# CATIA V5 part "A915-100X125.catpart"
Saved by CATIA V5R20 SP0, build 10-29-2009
Part number: A915-100X125
Source: Unknown
Property "A": "0.000"
Property "ARTICLENO": "A915-100X125"
Property "BOMINFO": "A915-100X125"
Property "CODE": "A915-100X125"
Property "CREATOR": "CADENAS GmbH"
Property "D": "13.500"
Property "D1": "20.000"
Property "FORM": "B"
Property "L": "125.000"
Property "L1": "25.000"
Property "L2": "75.000"
Property "LINA": "A915-100X125"
Property "NB": "A915-100X125"
Property "NBSYN": "$CODE."
Property "NN": "A915"
Property "NT": "VDI 3357 Wear Plates, steel"
Property "SCREW": "M12x25"
Property "SUPPLIER": "CF"
Property "T": "13.000"
Property "W": "100.000"
Bounding box of the stored display mesh (mm): x 0 to 20, y 0 to 125, z -50 to 50
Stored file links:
  C:\Users\borellobunino\Desktop\3D X SITO CF\A915\GSB_OILLESS_G22501100125\CATIAV5\A915-100X125.catpart
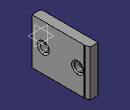
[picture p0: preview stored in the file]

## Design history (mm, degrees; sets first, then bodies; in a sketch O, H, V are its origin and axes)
Body1 "Geometry.1" (main body)
  Solid1 "A915-100X125.catpart": solid without history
